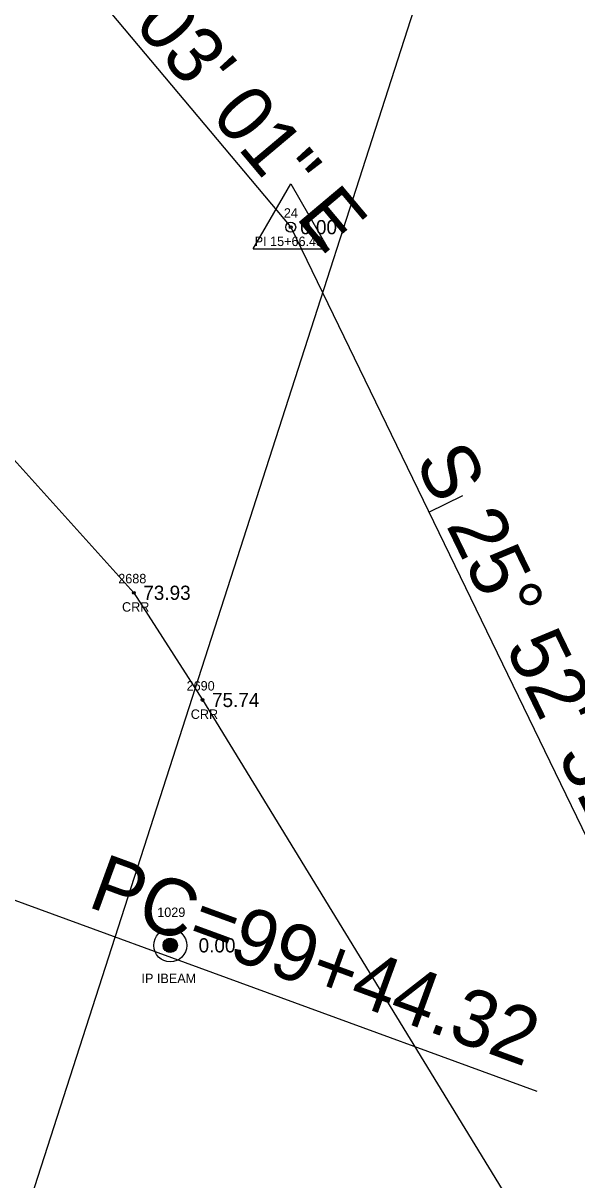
# Model space of a CAD drawing. Extents: x 2139392 to 2143384, y 505395 to 510520.
# Drawn here: x 2140725.6 to 2140784.2, y 508219 to 508341.4 of the extents above; entities that cross this region are included whole.
import ezdxf

# ---------------------------------------------------------------- set-up
doc = ezdxf.new("R2010")
doc.units = 0
for name, color, linetype in [('RD_EX_DV_Prop_txCode', 7, 'Continuous'), ('RD_EX_DV_PropPin', 7, 'Continuous'), ('RD_EX_H2O', 7, 'Continuous'), ('RD_EX_H2O_txCode', 7, 'Continuous'), ('RD_EX_TX_DV_Prop_ELEV', 7, 'Continuous'), ('RD_EX_TX_H2O_ELEV', 7, 'Continuous'), ('RD_EX_VEG', 7, 'Continuous'), ('RD_HC_Cl', 7, 'Continuous'), ('RD_HC_Data', 7, 'Continuous'), ('RD_HC_Data_Tic', 7, 'Continuous'), ('RD_HC_Survey_ELEV', 7, 'Continuous'), ('RD_HC_txCode', 7, 'Continuous'), ('RD_SMD_Locator', 7, 'Continuous')]:
    doc.layers.add(name, color=color, linetype=linetype)

msp = doc.modelspace()

# ---------------------------------------------------------------- linework, layer by layer
at = {"layer": 'RD_EX_DV_PropPin'}
for p, q in [((2140740.42, 508243.58), (2140740.42, 508243.98)), ((2140740.45, 508243.48), (2140740.45, 508244.08)), ((2140740.49, 508243.41), (2140740.49, 508244.15)), ((2140740.52, 508243.35), (2140740.52, 508244.21)), ((2140740.56, 508243.31), (2140740.56, 508244.25)), ((2140740.59, 508243.26), (2140740.59, 508244.29)), ((2140740.63, 508243.23), (2140740.63, 508244.33)), ((2140740.66, 508243.2), (2140740.66, 508244.36)), ((2140740.7, 508243.17), (2140740.7, 508244.39)), ((2140740.73, 508243.15), (2140740.73, 508244.41)), ((2140740.77, 508243.12), (2140740.77, 508244.44)), ((2140740.8, 508243.1), (2140740.8, 508244.46)), ((2140740.84, 508243.09), (2140740.84, 508244.47)), ((2140740.87, 508243.07), (2140740.87, 508244.49)), ((2140740.91, 508243.06), (2140740.91, 508244.5)), ((2140740.94, 508243.05), (2140740.94, 508244.51)), ((2140740.98, 508243.04), (2140740.98, 508244.52)), ((2140741.01, 508243.03), (2140741.01, 508244.53)), ((2140741.05, 508243.03), (2140741.05, 508244.53)), ((2140741.08, 508243.02), (2140741.08, 508244.54)), ((2140741.12, 508243.02), (2140741.12, 508244.54)), ((2140741.15, 508243.02), (2140741.15, 508244.54)), ((2140741.19, 508243.02), (2140741.19, 508244.54)), ((2140741.22, 508243.02), (2140741.22, 508244.54)), ((2140741.26, 508243.03), (2140741.26, 508244.53)), ((2140741.29, 508243.03), (2140741.29, 508244.53)), ((2140741.33, 508243.04), (2140741.33, 508244.52)), ((2140741.36, 508243.05), (2140741.36, 508244.51)), ((2140741.4, 508243.06), (2140741.4, 508244.5)), ((2140741.43, 508243.07), (2140741.43, 508244.49)), ((2140741.47, 508243.09), (2140741.47, 508244.47)), ((2140741.5, 508243.1), (2140741.5, 508244.46)), ((2140741.54, 508243.12), (2140741.54, 508244.44)), ((2140741.57, 508243.15), (2140741.57, 508244.41)), ((2140741.61, 508243.17), (2140741.61, 508244.39)), ((2140741.64, 508243.2), (2140741.64, 508244.36)), ((2140741.68, 508243.23), (2140741.68, 508244.33)), ((2140741.71, 508243.26), (2140741.71, 508244.29)), ((2140741.75, 508243.31), (2140741.75, 508244.25)), ((2140741.78, 508243.35), (2140741.78, 508244.21)), ((2140741.82, 508243.41), (2140741.82, 508244.15)), ((2140741.85, 508243.48), (2140741.85, 508244.08)), ((2140741.89, 508243.58), (2140741.89, 508243.98))]:
    msp.add_line(p, q, dxfattribs=at)
for radius in [1.75, 0.761]:
    msp.add_circle((2140741.15, 508243.78), radius, dxfattribs=at)
at = {"layer": 'RD_EX_H2O'}
msp.add_lwpolyline([(2140713.45, 508317.31), (2140716.63, 508306.71), (2140719.15, 508301.21), (2140737.29, 508281.1), (2140744.57, 508269.75), (2140792.9, 508190.84), (2140777.01, 508138.14), (2140787.07, 508130.01), (2140775.85, 508060.07), (2140818.22, 508047.21), (2140904.79, 508019.19), (2140978.29, 507974.61), (2141008.29, 508005.21), (2141024.7, 508023.32), (2141105.3, 508022.5)], dxfattribs=at)
at = {"layer": 'RD_EX_VEG'}
msp.add_lwpolyline([(2141197.74, 509262.45), (2141108.66, 509301.7), (2140947.3, 508831.92), (2140798.26, 508440.01), (2140718.9, 508193.9), (2140671.92, 508048.02), (2140772.34, 507989.74)], dxfattribs=at)
at = {"layer": 'RD_HC_Cl'}
for p, q in [((2140725.71, 508353.35), (2140753.91, 508319.8)), ((2140753.91, 508319.8), (2140802.1, 508220.46))]:
    msp.add_line(p, q, dxfattribs=at)
at = {"layer": 'RD_HC_Data'}
for p, q in [((2140749.94, 508317.51), (2140753.91, 508324.39)), ((2140753.91, 508324.39), (2140757.88, 508317.51)), ((2140749.94, 508317.51), (2140757.88, 508317.51)), ((2140670.51, 508268.37), (2140779.99, 508228.34))]:
    msp.add_line(p, q, dxfattribs=at)
msp.add_circle((2140753.91, 508319.8), 0.529, dxfattribs=at)
at = {"layer": 'RD_HC_Data_Tic'}
msp.add_line((2140768.54, 508289.64), (2140772.14, 508291.39), dxfattribs=at)
at = {"layer": 'RD_SMD_Locator'}
for centre in [(2140753.91, 508319.8), (2140737.29, 508281.1), (2140744.57, 508269.75), (2140741.15, 508243.78)]:
    msp.add_circle(centre, 0.15, dxfattribs=at)

# ---------------------------------------------------------------- texts
at = {"layer": 'RD_EX_DV_Prop_txCode'}
for s, p in [('1029', (2140739.77, 508246.78)), ('IP IBEAM', (2140738.1, 508239.78))]:
    msp.add_text(s, height=1, dxfattribs=at).set_placement(p)
at = {"layer": 'RD_EX_H2O_txCode'}
for s, p in [('2688', (2140735.64, 508282.1)), ('CRR', (2140736.04, 508279.1)), ('2690', (2140742.88, 508270.75)), ('CRR', (2140743.32, 508267.75))]:
    msp.add_text(s, height=1, dxfattribs=at).set_placement(p)
at = {"layer": 'RD_EX_TX_DV_Prop_ELEV'}
msp.add_text('0.00', height=1.5, dxfattribs=at).set_placement((2140744.15, 508243.03))
at = {"layer": 'RD_EX_TX_H2O_ELEV'}
for s, p in [('73.93', (2140738.29, 508280.35)), ('75.74', (2140745.57, 508269))]:
    msp.add_text(s, height=1.5, dxfattribs=at).set_placement(p)
at = {"layer": 'RD_HC_Data'}
for s, rotation, p in [('S 40%%d 03\' 01" E', 310.0502, (2140723.05, 508358.08)), ('S 25%%d 52\' 31" E', 295.8752, (2140767.02, 508295.08)), ('PC=99+44.32', 339.9158, (2140732.25, 508247.92))]:
    msp.add_text(s, height=6, rotation=rotation, dxfattribs=at).set_placement(p)
at = {"layer": 'RD_HC_Survey_ELEV'}
msp.add_text('0.00', height=1.5, dxfattribs=at).set_placement((2140754.91, 508319.05))
at = {"layer": 'RD_HC_txCode'}
for s, p in [('24', (2140753.18, 508320.8)), ('PI 15+66.48', (2140750.09, 508317.8))]:
    msp.add_text(s, height=1, dxfattribs=at).set_placement(p)

doc.saveas('drawing.dxf')
